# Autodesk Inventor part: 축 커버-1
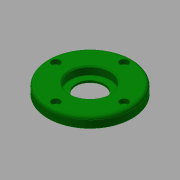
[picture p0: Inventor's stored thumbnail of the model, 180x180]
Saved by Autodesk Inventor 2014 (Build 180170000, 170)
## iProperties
Created: 2015-10
Part Number: 축 커버-1
Document SubType Name: Modeling
Designer: mdu
Density: 7.86 g/cm^3
Material: 강철, 연강
Appearance: Dark Green
Mass: 322.464 g
Surface Area: 133.703 cm^2
Volume: 41.026 cm^3
Author: mdu
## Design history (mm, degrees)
sketch "스케치1"
  geometry: C1 r 40 at (0, 0) reference; C2 r 26 at (0, 0) reference; 1 further point
  node "참조1"
  node "참조2"
extrude "돌출1" new body sketch "스케치1" distance "d0" = 10; taper "d1" = 0 deg
extrude "돌출2" join sketch "스케치1" distance "d2" = 3; taper "d3" = 0 deg
hole "구멍1" diameter "d6" = 27; stored, may be unused: countersink angle "d10" = 90 deg, drill point angle "d12" = 118 deg; dims "d4" = 10, "d5" = 10, "d7" = 6, "d8" = 38, "d9" = 8, "d11" = 8
sketch "스케치2"
  geometry: C1 r 20 at (0, 0); 1 further point
  constraints: 1 centre point, 1 coincident
  dimensions: "d13" = 40 diameter of C1
extrude "돌출3" cut sketch "스케치2" distance "d14" = 3; taper "d15" = 0 deg
sketch "스케치3"
  geometry: C1 r 1.621 at (0, 32.5) reference; 1 further point
hole "구멍2" sketch "스케치3" at (0, 32.5) diameter "d16" = 4.5; stored, may be unused: countersink angle "d20" = 90 deg, drill point angle "d22" = 118 deg; dims "d17" = 6, "d18" = 8, "d19" = 4.4, "d21" = 8
fillet "모깎기1" dims "d26" = 3, "d27" = 0.3
chamfer "모따기1" distance "d28" = 1; stored, may be unused: second distance "d29" = 2, angle "d30" = 45 deg
node "솔리드1"
pattern_circular "원형 패턴1" dims angle "d24" = 360 deg
node "참조3"
